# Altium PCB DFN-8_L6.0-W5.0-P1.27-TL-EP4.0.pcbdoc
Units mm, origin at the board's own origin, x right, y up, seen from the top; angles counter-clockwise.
Board outline 19.8 x 17.78 mm, 2 copper layers (Top Layer, Bottom Layer), stack 0 mm thick; 1 components, 0 nets, 9 pads, 0 vias.
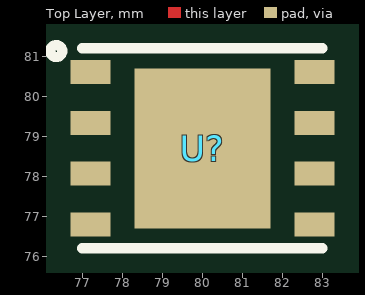
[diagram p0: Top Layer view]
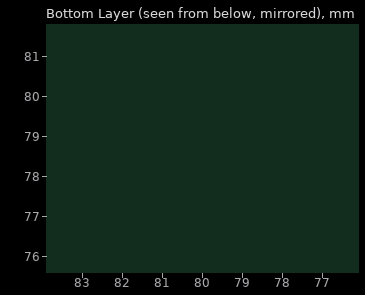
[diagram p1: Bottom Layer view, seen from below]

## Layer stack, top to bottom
Top Layer: signal copper (thickness not stored)
Bottom Layer: signal copper (thickness not stored)

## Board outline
89.65,69.85 69.85,69.85 69.85,87.63 89.65,87.63

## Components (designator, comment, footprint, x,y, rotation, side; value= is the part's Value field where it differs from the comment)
U? "" DFN-8_L6.0-W5.0-P1.27-TL-EP4.0 80,78.7 r0 top

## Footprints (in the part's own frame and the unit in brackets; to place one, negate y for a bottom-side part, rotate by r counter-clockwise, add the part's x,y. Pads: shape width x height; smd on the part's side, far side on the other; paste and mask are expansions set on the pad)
DFN-8_L6.0-W5.0-P1.27-TL-EP4.0 [mm]
  rect 1x0.6 smd: 1(-2.8,1.905) 2(-2.8,0.635) 3(-2.8,-0.635) 4(-2.8,-1.905) 5(2.8,-1.905) 6(2.8,-0.635) 7(2.8,0.635) 8(2.8,1.905)
  rect 3.4x4 smd: 9(0,0)
  silkscreen extent -3.8,-2.5 3,2.58

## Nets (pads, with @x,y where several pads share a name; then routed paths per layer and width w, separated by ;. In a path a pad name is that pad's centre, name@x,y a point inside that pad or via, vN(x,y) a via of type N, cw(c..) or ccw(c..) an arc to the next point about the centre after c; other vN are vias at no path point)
pads on no net: U?.1 U?.2 U?.3 U?.4 U?.5 U?.6 U?.7 U?.8 U?.9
